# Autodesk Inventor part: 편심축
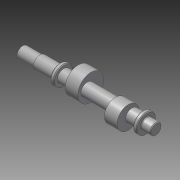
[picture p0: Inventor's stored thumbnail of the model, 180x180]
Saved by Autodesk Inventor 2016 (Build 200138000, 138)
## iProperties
Created: 2021-06
Part Number: 편심축
Material: 강철, 연강
Document SubType Name: Modeling
Designer: mdu-edu
Density: 7.86 g/cm^3
Appearance: 강철
Author: mdu-edu
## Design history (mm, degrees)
sketch "스케치1"
  geometry: L1 (0, 0)-(180, 0); L2 (180, 0)-(180, -7.5); L3 (180, -7.5)-(167, -7.5); L4 (167, -7.5)-(167, -13); L5 (167, -13)-(162, -13); L6 (162, -13)-(162, -8.5); L7 (162, -8.5)-(56, -8.5); L8 (56, -8.5)-(56, -13); L9 (56, -13)-(51, -13); L10 (51, -13)-(51, -8.5); L11 (51, -8.5)-(24, -8.5); L12 (24, -8.5)-(24, -7.5); L13 (24, -7.5)-(0, -7.5); L14 (0, -7.5)-(0, 0)
  constraints: 28 end point, 6 parallel, 3 horizontal, 3 vertical, 1 collinear, 1 perpendicular
  dimensions: "d0" = 15 diameter of L13 L1; "d2" = 26 diameter of L9 L1; "d3" = 26 diameter of L5 L1; "d4" = 15 diameter of L3 L1; "d5" = 17 diameter of L7 L1; "d6" = 17 diameter of L11 L1; "d7" = 24 distance between parallel lines of L12 L14; "d8" = 51 distance between parallel lines of L14 L10; "d10" = 5 distance of L8.end L9.end; "d11" = 5 distance of L4.end L5.end; "d12" = 13 distance between parallel lines of L4 L2; "d13" = 180 distance between parallel lines of L14 L2
revolve "회전1" sketch "스케치1" stored, may be unused: angle "d14" = 90 deg
node "작업 평면1"
sketch "스케치2"
  geometry: C1 r 17.5 at (0, 5); 1 further point
  constraints: 1 centre point, 1 vertical alignment
  dimensions: "d16" = 35 diameter of C1; "d17" = 5 distance of C1.centre point (0, 0)
extrude "돌출1" join sketch "스케치2" distance "d18" = 17; taper "d19" = 0 deg
node "작업 평면2"
sketch "스케치3"
  geometry: C1 r 15 at (0, -5); 1 further point
  constraints: 1 centre point, 1 vertical alignment
  dimensions: "d21" = 30 diameter of C1; "d22" = 5 distance of point (0, 0) C1.centre
extrude "돌출2" join sketch "스케치3" distance "d23" = 17; taper "d24" = 0 deg
chamfer "모따기1" distance "d29" = 1; stored, may be unused: second distance "d30" = 2, angle "d31" = 45 deg
node "작업 평면3"
sketch "스케치4"
  geometry: L1 (-5.5, 2.5)-(12, 2.5); L2 (12, 2.5)-(12, -2.5); L3 (12, -2.5)-(-5.5, -2.5); L4 (12, 6.5)-(12, -6.5) reference; A1 r 2.5 centre (-5.5, 0) between (-5.5, 2.5) and (-5.5, -2.5); 1 further point
  constraints: 6 end point, 2 point on circle, 2 tangent, 1 centre point, 1 collinear, 1 horizontal, 1 horizontal alignment, 1 midpoint, 1 parallel, 1 perpendicular
  dimensions: "d25" = 5 diameter of A1; "d32" = 20 dimension on A1 L4
extrude "돌출3" cut sketch "스케치4" distance "d27" = 3; taper "d28" = 0 deg
fillet "모깎기1" dims "d33" = 0.6
fillet "모깎기2" dims "d34" = 1
node "솔리드1"
other parameters: "d15" = -70.5, "d20" = -32.5
